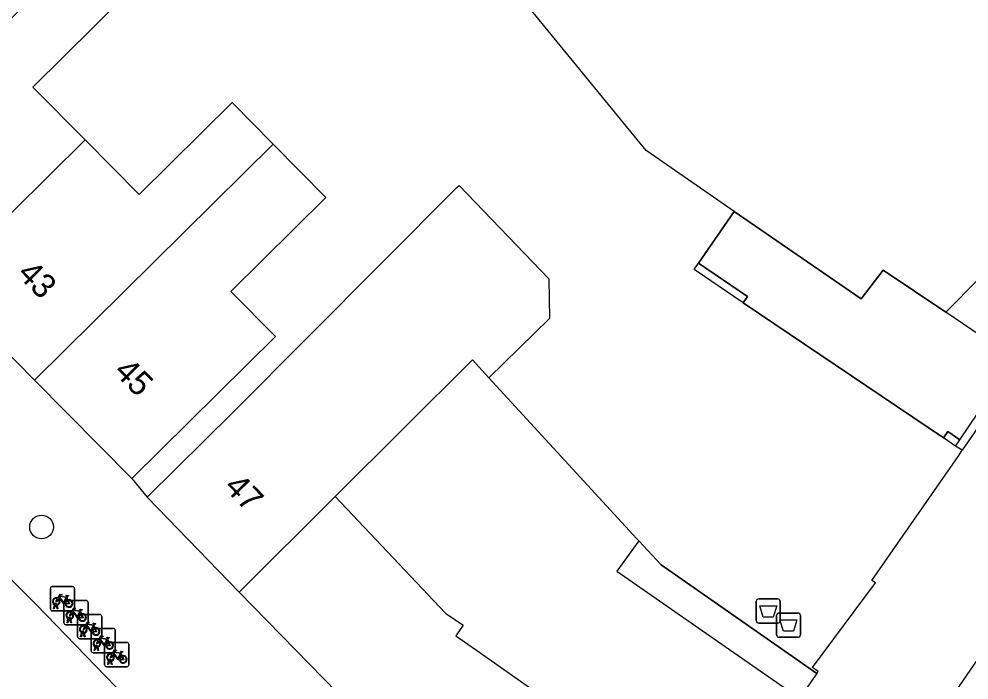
# Model space of a CAD drawing. Extents: x 160107 to 160928, y 382056 to 382918.
# Drawn here: x 160728.34 to 160767.62, y 382574.96 to 382602.28 of the extents above; entities that cross this region are included whole.
import ezdxf

# ---------------------------------------------------------------- set-up
doc = ezdxf.new("R2010")
doc.units = 0
for name, color, linetype in [('IMGEO_Afval_apart_plaats', 7, 'Continuous'), ('IMGEO_Boom', 7, 'Continuous'), ('IMGEO_Erf', 7, 'Continuous'), ('IMGEO_Fietsenrek', 7, 'Continuous'), ('IMGEO_Muur', 7, 'Continuous'), ('IMGEO_Pand', 7, 'Continuous'), ('IMGEO_Pand_nummerreeks', 7, 'Continuous'), ('IMGEO_Pand_overbouw', 7, 'Continuous'), ('IMGEO_Rijbaan_lokaal_gesloten', 7, 'Continuous'), ('IMGEO_Rijbaan_lokaal_open', 7, 'Continuous'), ('IMGEO_Voetpad_open', 7, 'Continuous')]:
    doc.layers.add(name, color=color, linetype=linetype)

msp = doc.modelspace()

# ---------------------------------------------------------------- linework, layer by layer
at = {"layer": 'IMGEO_Afval_apart_plaats'}
for p, q in [((160758.824, 382577.409), (160758.824, 382578.209)), ((160758.824, 382578.209), (160758.824, 382577.409)), ((160758.924, 382578.309), (160759.714, 382578.309)), ((160759.714, 382578.309), (160758.924, 382578.309)), ((160759.814, 382578.209), (160759.814, 382577.409)), ((160759.814, 382577.409), (160759.814, 382578.209)), ((160759.661, 382576.825), (160759.661, 382577.625)), ((160759.661, 382577.625), (160759.661, 382576.825)), ((160759.761, 382577.725), (160760.551, 382577.725)), ((160760.551, 382577.725), (160759.761, 382577.725)), ((160760.651, 382577.625), (160760.651, 382576.825)), ((160760.651, 382576.825), (160760.651, 382577.625)), ((160759.714, 382577.309), (160758.924, 382577.309)), ((160758.924, 382577.309), (160759.714, 382577.309)), ((160760.551, 382576.725), (160759.761, 382576.725)), ((160759.761, 382576.725), (160760.551, 382576.725))]:
    msp.add_line(p, q, dxfattribs=at)
for points in [[(160758.967, 382578.023), (160759.671, 382578.023), (160759.522, 382577.553), (160759.116, 382577.553), (160758.967, 382578.023)], [(160759.804, 382577.439), (160760.508, 382577.439), (160760.359, 382576.969), (160759.953, 382576.969), (160759.804, 382577.439)]]:
    msp.add_lwpolyline(points, dxfattribs=at)
for centre, start, end in [((160758.924, 382578.209), 90, 180), ((160758.924, 382578.209), 90, 180), ((160759.714, 382578.209), 0, 90), ((160759.714, 382578.209), 360, 90), ((160759.761, 382577.625), 90, 180), ((160759.761, 382577.625), 90, 180), ((160760.551, 382577.625), 0, 90), ((160760.551, 382577.625), 360, 90), ((160758.924, 382577.409), 180, 270), ((160758.924, 382577.409), 180, 270), ((160759.714, 382577.409), 270, 0), ((160759.714, 382577.409), 270, 0), ((160759.761, 382576.825), 180, 270), ((160759.761, 382576.825), 180, 270), ((160760.551, 382576.825), 270, 0), ((160760.551, 382576.825), 270, 0)]:
    msp.add_arc(centre, 0.1, start, end, dxfattribs=at)
at = {"layer": 'IMGEO_Boom'}
msp.add_circle((160729.272, 382581.28), 0.489, dxfattribs=at)
at = {"layer": 'IMGEO_Erf'}
msp.add_lwpolyline([(160753.97, 382580.704), (160754.898, 382579.722), (160761.329, 382575.219)], dxfattribs=at)
at = {"layer": 'IMGEO_Fietsenrek'}
for p, q in [((160729.712, 382578.817), (160730.553, 382578.817)), ((160730.553, 382578.817), (160729.712, 382578.817)), ((160729.637, 382577.892), (160729.637, 382578.733)), ((160729.637, 382578.733), (160729.637, 382577.892)), ((160730.324, 382578.366), (160730.36, 382578.271)), ((160730.637, 382578.742), (160730.637, 382577.901)), ((160730.637, 382577.901), (160730.637, 382578.742)), ((160729.764, 382577.901), (160729.803, 382578.061)), ((160729.833, 382578.049), (160729.798, 382577.901)), ((160729.875, 382578.073), (160729.874, 382578.077)), ((160729.916, 382577.901), (160729.882, 382578.043)), ((160729.906, 382578.084), (160729.907, 382578.077)), ((160729.914, 382578.047), (160729.949, 382577.901)), ((160730.198, 382577.315), (160730.198, 382578.156)), ((160730.198, 382578.156), (160730.198, 382577.315)), ((160730.273, 382578.24), (160731.114, 382578.24)), ((160731.114, 382578.24), (160730.273, 382578.24)), ((160731.198, 382578.165), (160731.198, 382577.324)), ((160731.198, 382577.324), (160731.198, 382578.165)), ((160730.562, 382577.817), (160729.721, 382577.817)), ((160729.721, 382577.817), (160730.562, 382577.817)), ((160729.798, 382577.901), (160729.764, 382577.901)), ((160729.949, 382577.901), (160729.916, 382577.901)), ((160730.834, 382577.662), (160731.675, 382577.662)), ((160731.675, 382577.662), (160730.834, 382577.662)), ((160730.885, 382577.789), (160730.921, 382577.694)), ((160731.759, 382577.587), (160731.759, 382576.746)), ((160731.759, 382576.746), (160731.759, 382577.587)), ((160731.123, 382577.24), (160730.282, 382577.24)), ((160730.282, 382577.24), (160731.123, 382577.24)), ((160730.325, 382577.324), (160730.364, 382577.484)), ((160730.359, 382577.324), (160730.325, 382577.324)), ((160730.394, 382577.472), (160730.359, 382577.324)), ((160730.436, 382577.496), (160730.435, 382577.5)), ((160730.477, 382577.324), (160730.443, 382577.466)), ((160730.467, 382577.507), (160730.468, 382577.5)), ((160730.475, 382577.47), (160730.51, 382577.324)), ((160730.51, 382577.324), (160730.477, 382577.324)), ((160730.759, 382576.737), (160730.759, 382577.578)), ((160730.759, 382577.578), (160730.759, 382576.737)), ((160731.446, 382577.211), (160731.482, 382577.116)), ((160730.886, 382576.746), (160730.925, 382576.906)), ((160730.955, 382576.894), (160730.92, 382576.746)), ((160730.997, 382576.918), (160730.996, 382576.922)), ((160731.038, 382576.746), (160731.004, 382576.888)), ((160731.028, 382576.929), (160731.029, 382576.922)), ((160731.036, 382576.892), (160731.071, 382576.746)), ((160731.319, 382576.16), (160731.319, 382577.001)), ((160731.319, 382577.001), (160731.319, 382576.16)), ((160731.394, 382577.085), (160732.235, 382577.085)), ((160732.235, 382577.085), (160731.394, 382577.085)), ((160732.319, 382577.01), (160732.319, 382576.169)), ((160732.319, 382576.169), (160732.319, 382577.01)), ((160731.684, 382576.662), (160730.843, 382576.662)), ((160730.843, 382576.662), (160731.684, 382576.662)), ((160730.92, 382576.746), (160730.886, 382576.746)), ((160731.071, 382576.746), (160731.038, 382576.746)), ((160731.88, 382575.582), (160731.88, 382576.423)), ((160731.88, 382576.423), (160731.88, 382575.582)), ((160731.955, 382576.507), (160732.796, 382576.507)), ((160732.796, 382576.507), (160731.955, 382576.507)), ((160732.006, 382576.634), (160732.042, 382576.539)), ((160732.88, 382576.432), (160732.88, 382575.591)), ((160732.88, 382575.591), (160732.88, 382576.432)), ((160732.244, 382576.085), (160731.403, 382576.085)), ((160731.403, 382576.085), (160732.244, 382576.085)), ((160731.446, 382576.169), (160731.485, 382576.329)), ((160731.48, 382576.169), (160731.446, 382576.169)), ((160731.515, 382576.317), (160731.48, 382576.169)), ((160731.557, 382576.341), (160731.556, 382576.345)), ((160731.598, 382576.169), (160731.564, 382576.311)), ((160731.588, 382576.352), (160731.589, 382576.345)), ((160731.596, 382576.315), (160731.631, 382576.169)), ((160731.631, 382576.169), (160731.598, 382576.169)), ((160732.567, 382576.056), (160732.603, 382575.961)), ((160732.007, 382575.591), (160732.046, 382575.751)), ((160732.076, 382575.739), (160732.041, 382575.591)), ((160732.118, 382575.763), (160732.117, 382575.767)), ((160732.159, 382575.591), (160732.125, 382575.733)), ((160732.149, 382575.774), (160732.15, 382575.767)), ((160732.157, 382575.737), (160732.192, 382575.591)), ((160732.805, 382575.507), (160731.964, 382575.507)), ((160731.964, 382575.507), (160732.805, 382575.507)), ((160732.041, 382575.591), (160732.007, 382575.591)), ((160732.192, 382575.591), (160732.159, 382575.591))]:
    msp.add_line(p, q, dxfattribs=at)
for points in [[(160729.95, 382578.343), (160730.045, 382578.507), (160730.131, 382578.493), (160730.133, 382578.484), (160730.077, 382578.473), (160730.05, 382578.428), (160730.306, 382578.387)], [(160730.293, 382578.362), (160730.036, 382578.403), (160730.019, 382578.374), (160730.186, 382578.154), (160730.293, 382578.362)], [(160730.306, 382578.387), (160730.331, 382578.436), (160730.325, 382578.44), (160730.302, 382578.444), (160730.29, 382578.451), (160730.289, 382578.454), (160730.291, 382578.459), (160730.386, 382578.444), (160730.388, 382578.434), (160730.378, 382578.421), (160730.366, 382578.415), (160730.352, 382578.421), (160730.324, 382578.366)], [(160729.971, 382578.291), (160729.919, 382578.201), (160729.879, 382578.176), (160729.88, 382578.223), (160729.935, 382578.317)], [(160730.246, 382578.099), (160730.196, 382578.099), (160730.005, 382578.35), (160729.986, 382578.318)], [(160730.341, 382578.264), (160730.311, 382578.341), (160730.202, 382578.123), (160730.245, 382578.123)], [(160730.275, 382578.123), (160730.395, 382578.122), (160730.351, 382578.236)], [(160730.371, 382578.243), (160730.426, 382578.098), (160730.276, 382578.098)], [(160730.532, 382577.714), (160730.48, 382577.624), (160730.44, 382577.599), (160730.441, 382577.646), (160730.496, 382577.74)], [(160730.511, 382577.766), (160730.606, 382577.93), (160730.692, 382577.916), (160730.694, 382577.907), (160730.638, 382577.896), (160730.611, 382577.851), (160730.867, 382577.81)], [(160730.807, 382577.522), (160730.757, 382577.522), (160730.566, 382577.773), (160730.547, 382577.741)], [(160730.854, 382577.785), (160730.597, 382577.826), (160730.58, 382577.797), (160730.747, 382577.577), (160730.854, 382577.785)], [(160730.902, 382577.687), (160730.872, 382577.764), (160730.763, 382577.546), (160730.806, 382577.546)], [(160730.836, 382577.546), (160730.956, 382577.545), (160730.912, 382577.659)], [(160730.932, 382577.666), (160730.987, 382577.521), (160730.837, 382577.521)], [(160730.867, 382577.81), (160730.892, 382577.859), (160730.886, 382577.863), (160730.863, 382577.867), (160730.851, 382577.874), (160730.85, 382577.877), (160730.852, 382577.882), (160730.947, 382577.867), (160730.949, 382577.857), (160730.939, 382577.844), (160730.927, 382577.838), (160730.913, 382577.844), (160730.885, 382577.789)], [(160731.072, 382577.188), (160731.167, 382577.352), (160731.253, 382577.338), (160731.255, 382577.329), (160731.199, 382577.318), (160731.172, 382577.273), (160731.428, 382577.232)], [(160731.368, 382576.944), (160731.318, 382576.944), (160731.127, 382577.195), (160731.108, 382577.163)], [(160731.415, 382577.207), (160731.158, 382577.248), (160731.141, 382577.219), (160731.308, 382576.999), (160731.415, 382577.207)], [(160731.463, 382577.109), (160731.433, 382577.186), (160731.324, 382576.968), (160731.367, 382576.968)], [(160731.428, 382577.232), (160731.453, 382577.281), (160731.447, 382577.285), (160731.424, 382577.289), (160731.412, 382577.296), (160731.411, 382577.299), (160731.413, 382577.304), (160731.508, 382577.289), (160731.51, 382577.279), (160731.5, 382577.266), (160731.488, 382577.26), (160731.474, 382577.266), (160731.446, 382577.211)], [(160731.093, 382577.136), (160731.041, 382577.046), (160731.001, 382577.021), (160731.002, 382577.068), (160731.057, 382577.162)], [(160731.397, 382576.968), (160731.517, 382576.967), (160731.473, 382577.081)], [(160731.493, 382577.088), (160731.548, 382576.943), (160731.398, 382576.943)], [(160731.653, 382576.559), (160731.601, 382576.469), (160731.561, 382576.444), (160731.562, 382576.491), (160731.617, 382576.585)], [(160731.632, 382576.611), (160731.727, 382576.775), (160731.813, 382576.761), (160731.815, 382576.752), (160731.759, 382576.741), (160731.732, 382576.696), (160731.988, 382576.655)], [(160731.928, 382576.367), (160731.878, 382576.367), (160731.687, 382576.618), (160731.668, 382576.586)], [(160731.975, 382576.63), (160731.718, 382576.671), (160731.701, 382576.642), (160731.868, 382576.422), (160731.975, 382576.63)], [(160732.023, 382576.532), (160731.993, 382576.609), (160731.884, 382576.391), (160731.927, 382576.391)], [(160731.957, 382576.391), (160732.077, 382576.39), (160732.033, 382576.504)], [(160732.053, 382576.511), (160732.108, 382576.366), (160731.958, 382576.366)], [(160731.988, 382576.655), (160732.013, 382576.704), (160732.007, 382576.708), (160731.984, 382576.712), (160731.972, 382576.719), (160731.971, 382576.722), (160731.973, 382576.727), (160732.068, 382576.712), (160732.07, 382576.702), (160732.06, 382576.689), (160732.048, 382576.683), (160732.034, 382576.689), (160732.006, 382576.634)], [(160732.214, 382575.981), (160732.162, 382575.891), (160732.122, 382575.866), (160732.123, 382575.913), (160732.178, 382576.007)], [(160732.193, 382576.033), (160732.288, 382576.197), (160732.374, 382576.183), (160732.376, 382576.174), (160732.32, 382576.163), (160732.293, 382576.118), (160732.549, 382576.077)], [(160732.489, 382575.789), (160732.439, 382575.789), (160732.248, 382576.04), (160732.229, 382576.008)], [(160732.536, 382576.052), (160732.279, 382576.093), (160732.262, 382576.064), (160732.429, 382575.844), (160732.536, 382576.052)], [(160732.584, 382575.954), (160732.554, 382576.031), (160732.445, 382575.813), (160732.488, 382575.813)], [(160732.549, 382576.077), (160732.574, 382576.126), (160732.568, 382576.13), (160732.545, 382576.134), (160732.533, 382576.141), (160732.532, 382576.144), (160732.534, 382576.149), (160732.629, 382576.134), (160732.631, 382576.124), (160732.621, 382576.111), (160732.609, 382576.105), (160732.595, 382576.111), (160732.567, 382576.056)], [(160732.518, 382575.813), (160732.638, 382575.812), (160732.594, 382575.926)], [(160732.614, 382575.933), (160732.669, 382575.788), (160732.519, 382575.788)]]:
    msp.add_lwpolyline(points, dxfattribs=at)
for centre, radius, start, end in [((160729.715, 382578.739), 0.0779, 92.4484, 184.2845), ((160729.715, 382578.739), 0.0779, 92.4484, 184.2845), ((160730.559, 382578.739), 0.0779, 2.4484, 94.2845), ((160730.559, 382578.739), 0.0779, 2.4484, 94.2845), ((160729.877, 382578.202), 0.159, 62.6766, 242.1369), ((160729.877, 382578.202), 0.129, 63.3192, 238.903), ((160729.857, 382578.073), 0.0499, 12.8025, 158.6934), ((160729.877, 382578.202), 0.159, 253.9967, 271.7867), ((160729.857, 382578.073), 0.0174, 12.8025, 163.4502), ((160729.877, 382578.202), 0.129, 253.415, 269.0204), ((160729.877, 382578.202), 0.129, 283.6043, 43.4302), ((160729.877, 382578.202), 0.159, 283.5766, 46.6042), ((160730.276, 382578.162), 0.0779, 92.4484, 184.2845), ((160730.276, 382578.162), 0.0779, 92.4484, 184.2845), ((160730.404, 382578.118), 0.159, 113.3408, 178.3217), ((160730.404, 382578.118), 0.159, 187.0065, 105.7708), ((160730.404, 382578.118), 0.129, 113.923, 177.9556), ((160730.404, 382578.118), 0.129, 188.6715, 104.5883), ((160731.12, 382578.162), 0.0779, 2.4484, 94.2845), ((160731.12, 382578.162), 0.0779, 2.4484, 94.2845), ((160729.715, 382577.895), 0.0779, 182.4484, 274.2845), ((160729.715, 382577.895), 0.0779, 182.4484, 274.2845), ((160730.438, 382577.625), 0.159, 62.6766, 242.1369), ((160730.438, 382577.625), 0.129, 63.3192, 238.903), ((160730.438, 382577.625), 0.129, 283.6043, 43.4302), ((160730.438, 382577.625), 0.159, 283.5766, 46.6042), ((160730.559, 382577.895), 0.0779, 272.4484, 4.2845), ((160730.559, 382577.895), 0.0779, 272.4484, 4.2845), ((160730.837, 382577.584), 0.0779, 92.4484, 184.2845), ((160730.837, 382577.584), 0.0779, 92.4484, 184.2845), ((160730.965, 382577.541), 0.159, 113.3408, 178.3217), ((160730.965, 382577.541), 0.159, 187.0065, 105.7708), ((160730.965, 382577.541), 0.129, 113.923, 177.9556), ((160730.965, 382577.541), 0.129, 188.6715, 104.5883), ((160731.681, 382577.584), 0.0779, 2.4484, 94.2845), ((160731.681, 382577.584), 0.0779, 2.4484, 94.2845), ((160730.276, 382577.318), 0.0779, 182.4484, 274.2845), ((160730.276, 382577.318), 0.0779, 182.4484, 274.2845), ((160730.418, 382577.496), 0.0499, 12.8025, 158.6934), ((160730.438, 382577.625), 0.159, 253.9967, 271.7867), ((160730.418, 382577.496), 0.0174, 12.8025, 163.4502), ((160730.438, 382577.625), 0.129, 253.415, 269.0204), ((160730.999, 382577.047), 0.159, 62.6766, 242.1369), ((160731.12, 382577.318), 0.0779, 272.4484, 4.2845), ((160731.12, 382577.318), 0.0779, 272.4484, 4.2845), ((160730.999, 382577.047), 0.129, 63.3192, 238.903), ((160730.979, 382576.918), 0.0499, 12.8025, 158.6934), ((160730.999, 382577.047), 0.159, 253.9967, 271.7867), ((160730.979, 382576.918), 0.0174, 12.8025, 163.4502), ((160730.999, 382577.047), 0.129, 253.415, 269.0204), ((160730.999, 382577.047), 0.129, 283.6043, 43.4302), ((160730.999, 382577.047), 0.159, 283.5766, 46.6042), ((160731.397, 382577.007), 0.0779, 92.4484, 184.2845), ((160731.397, 382577.007), 0.0779, 92.4484, 184.2845), ((160731.526, 382576.963), 0.159, 113.3408, 178.3217), ((160731.526, 382576.963), 0.159, 187.0065, 105.7708), ((160731.526, 382576.963), 0.129, 113.923, 177.9556), ((160731.526, 382576.963), 0.129, 188.6715, 104.5883), ((160732.241, 382577.007), 0.0779, 2.4484, 94.2845), ((160732.241, 382577.007), 0.0779, 2.4484, 94.2845), ((160730.837, 382576.74), 0.0779, 182.4484, 274.2845), ((160730.837, 382576.74), 0.0779, 182.4484, 274.2845), ((160731.559, 382576.47), 0.159, 62.6766, 242.1369), ((160731.559, 382576.47), 0.129, 63.3192, 238.903), ((160731.559, 382576.47), 0.129, 283.6043, 43.4302), ((160731.559, 382576.47), 0.159, 283.5766, 46.6042), ((160731.681, 382576.74), 0.0779, 272.4484, 4.2845), ((160731.681, 382576.74), 0.0779, 272.4484, 4.2845), ((160731.958, 382576.429), 0.0779, 92.4484, 184.2845), ((160731.958, 382576.429), 0.0779, 92.4484, 184.2845), ((160732.086, 382576.386), 0.159, 113.3408, 178.3217), ((160732.086, 382576.386), 0.159, 187.0065, 105.7708), ((160732.086, 382576.386), 0.129, 113.923, 177.9556), ((160732.086, 382576.386), 0.129, 188.6715, 104.5883), ((160732.802, 382576.429), 0.0779, 2.4484, 94.2845), ((160732.802, 382576.429), 0.0779, 2.4484, 94.2845), ((160731.397, 382576.163), 0.0779, 182.4484, 274.2845), ((160731.397, 382576.163), 0.0779, 182.4484, 274.2845), ((160731.539, 382576.341), 0.0499, 12.8025, 158.6934), ((160731.559, 382576.47), 0.159, 253.9967, 271.7867), ((160731.539, 382576.341), 0.0174, 12.8025, 163.4502), ((160731.559, 382576.47), 0.129, 253.415, 269.0204), ((160732.12, 382575.892), 0.159, 62.6766, 242.1369), ((160732.12, 382575.892), 0.129, 63.3192, 238.903), ((160732.12, 382575.892), 0.159, 283.5766, 46.6042), ((160732.241, 382576.163), 0.0779, 272.4484, 4.2845), ((160732.241, 382576.163), 0.0779, 272.4484, 4.2845), ((160732.1, 382575.763), 0.0499, 12.8025, 158.6934), ((160732.12, 382575.892), 0.159, 253.9967, 271.7867), ((160732.1, 382575.763), 0.0174, 12.8025, 163.4502), ((160732.12, 382575.892), 0.129, 253.415, 269.0204), ((160732.12, 382575.892), 0.129, 283.6043, 43.4302), ((160732.647, 382575.808), 0.159, 113.3408, 178.3217), ((160732.647, 382575.808), 0.159, 187.0065, 105.7708), ((160732.647, 382575.808), 0.129, 113.923, 177.9556), ((160732.647, 382575.808), 0.129, 188.6715, 104.5883), ((160731.958, 382575.585), 0.0779, 182.4484, 274.2845), ((160731.958, 382575.585), 0.0779, 182.4484, 274.2845), ((160732.802, 382575.585), 0.0779, 272.4484, 4.2845), ((160732.802, 382575.585), 0.0779, 272.4484, 4.2845)]:
    msp.add_arc(centre, radius, start, end, dxfattribs=at)
at = {"layer": 'IMGEO_Muur'}
msp.add_lwpolyline([(160761.329, 382575.219), (160754.898, 382579.722), (160753.97, 382580.704)], dxfattribs=at)
at = {"layer": 'IMGEO_Pand'}
for points in [[(160757.915, 382594.327), (160754.266, 382596.84), (160747.353, 382605.306), (160742.894, 382610.767), (160744.207, 382630.725), (160757.68, 382644.347), (160763.102, 382639.177)], [(160721.02, 382595.398), (160724.575, 382598.915), (160730.892, 382605.166), (160733.062, 382607.274), (160734.912, 382605.405), (160732.761, 382603.276), (160728.91, 382599.465), (160731.069, 382597.284)], [(160757.915, 382594.327), (160763.168, 382590.709), (160764.076, 382591.898), (160766.66, 382590.155), (160779.038, 382602.663)], [(160731.069, 382597.284), (160733.308, 382595.021), (160737.154, 382598.827), (160738.853, 382597.11)], [(160731.069, 382597.284), (160725.048, 382591.328)], [(160728.986, 382587.348), (160738.853, 382597.11)], [(160738.853, 382597.11), (160741.033, 382594.907), (160737.099, 382591.015), (160738.941, 382589.154), (160736.563, 382586.801), (160733.008, 382583.284)], [(160733.642, 382582.516), (160737.197, 382586.033), (160746.447, 382595.309), (160746.535, 382595.394), (160750.25, 382591.543), (160750.277, 382589.904), (160747.769, 382587.449)], [(160758.286, 382590.546), (160756.252, 382591.918), (160756.434, 382592.182)], [(160758.286, 382590.546), (160758.468, 382590.81), (160756.434, 382592.182)], [(160728.986, 382587.348), (160725.048, 382591.328)], [(160747.769, 382587.449), (160747.09, 382588.188), (160741.408, 382582.536)], [(160747.769, 382587.449), (160753.882, 382580.798), (160753.97, 382580.704)], [(160733.008, 382583.284), (160728.986, 382587.348)], [(160767.067, 382584.623), (160767.246, 382584.889), (160766.74, 382585.23), (160766.561, 382584.965)], [(160767.067, 382584.623), (160766.561, 382584.965)], [(160737.437, 382578.588), (160733.642, 382582.516)], [(160741.408, 382582.536), (160737.437, 382578.588)], [(160741.408, 382582.536), (160745.973, 382577.722), (160746.703, 382577.218), (160746.405, 382576.787), (160747.26, 382576.186), (160757.182, 382569.207)], [(160753.97, 382580.704), (160753.062, 382579.456), (160760.618, 382574.2)], [(160753.452, 382563.788), (160748.671, 382567.101), (160745.569, 382570.268), (160737.437, 382578.588)]]:
    msp.add_lwpolyline(points, dxfattribs=at)
at = {"layer": 'IMGEO_Pand_overbouw'}
msp.add_lwpolyline([(160764.076, 382591.898), (160763.168, 382590.709), (160757.915, 382594.327), (160756.434, 382592.182), (160758.468, 382590.81), (160758.286, 382590.546), (160766.561, 382584.965), (160766.74, 382585.23), (160767.246, 382584.889), (160769.504, 382588.236), (160766.66, 382590.155)], close=True, dxfattribs=at)
at = {"layer": 'IMGEO_Rijbaan_lokaal_gesloten'}
msp.add_lwpolyline([(160787.691, 382604.499), (160763.257, 382568.959)], dxfattribs=at)
at = {"layer": 'IMGEO_Rijbaan_lokaal_open'}
msp.add_lwpolyline([(160727.5, 382579.611), (160729.043, 382578.08), (160732.75, 382574.262), (160733.244, 382573.838), (160736.054, 382571.254)], dxfattribs=at)
at = {"layer": 'IMGEO_Voetpad_open'}
for points in [[(160780.249, 382603.067), (160780.054, 382602.786), (160769.686, 382587.844), (160769.298, 382587.285), (160767.334, 382584.454)], [(160756.434, 382592.182), (160757.915, 382594.327)], [(160766.561, 382584.965), (160758.286, 382590.546)], [(160761.329, 382575.219), (160761.386, 382575.301), (160761.155, 382575.469), (160763.749, 382578.97), (160763.609, 382579.073), (160767.172, 382584.194), (160767.334, 382584.454)], [(160767.334, 382584.454), (160767.067, 382584.623)], [(160733.008, 382583.284), (160733.642, 382582.516)], [(160761.329, 382575.219), (160760.618, 382574.2)]]:
    msp.add_lwpolyline(points, dxfattribs=at)

# ---------------------------------------------------------------- texts
at = {"layer": 'IMGEO_Pand_nummerreeks'}
for s, rotation, p in [('43', 314.7005, (160728.224, 382591.701)), ('45', 314.7005, (160732.22, 382587.663)), ('47', 314.0144, (160736.777, 382582.897))]:
    msp.add_text(s, height=1, rotation=rotation, dxfattribs=at).set_placement(p)

doc.saveas('drawing.dxf')
